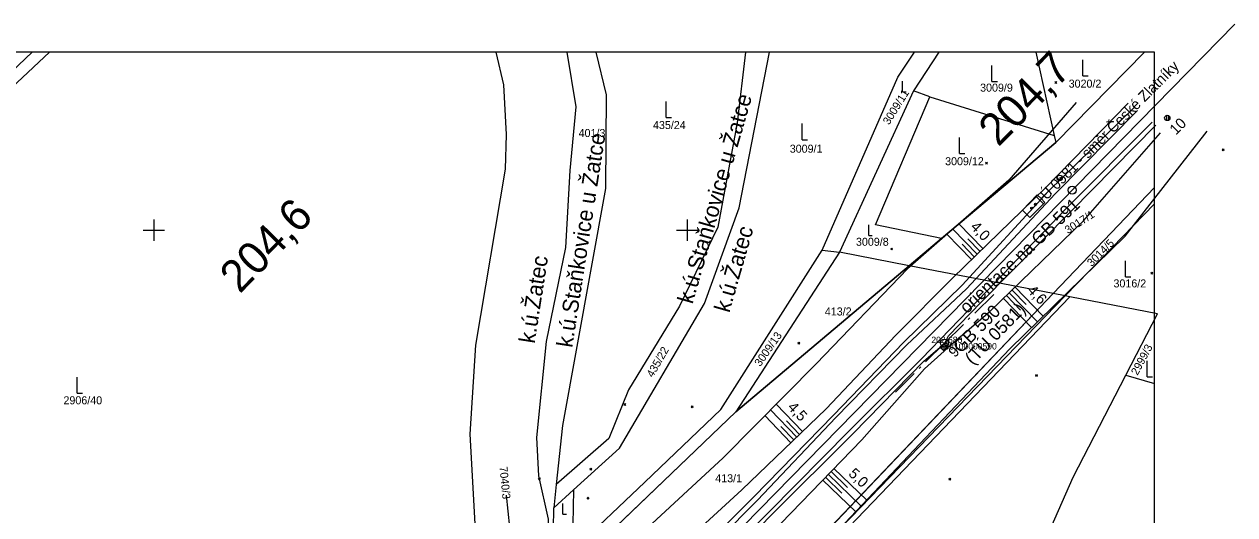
# Model space of a CAD drawing. Extents: x -800194 to -799078, y -1007177 to -1006597.
# Drawn here: x -799524.3 to -799297.3, y -1006853.3 to -1006761.4 of the extents above; entities that cross this region are included whole.
import ezdxf

# ---------------------------------------------------------------- set-up
doc = ezdxf.new("R2010")
doc.units = 0
for name, color, linetype in [('02_Osa_koleje', 7, 'Continuous'), ('Legenda 1', 7, 'Continuous'), ('Ramove udaje', 7, 'Continuous'), ('Vrstva 1', 7, 'Continuous'), ('Vrstva 11', 7, 'Continuous'), ('Vrstva 12', 7, 'Continuous'), ('Vrstva 4', 7, 'Continuous'), ('Vrstva 48', 7, 'Continuous'), ('Vrstva 49', 7, 'Continuous'), ('Vrstva 53', 7, 'Continuous'), ('Vrstva 55', 7, 'Continuous'), ('Vrstva 57', 7, 'Continuous'), ('Vrstva 58', 7, 'Continuous'), ('Vrstva 60', 7, 'Continuous'), ('Vrstva 61', 7, 'Continuous'), ('Vrstva 63', 7, 'Continuous'), ('Vrstva 7', 7, 'Continuous')]:
    doc.layers.add(name, color=color, linetype=linetype)

msp = doc.modelspace()

# ---------------------------------------------------------------- linework, layer by layer
at = {"layer": 'Legenda 1'}
msp.add_lwpolyline([(-800193.4, -1007176.65), (-799312.4, -1007176.65), (-799312.4, -1006766.65), (-800193.4, -1006766.65)], close=True, dxfattribs=at)
at = {"layer": 'Ramove udaje'}
for p, q in [((-799500, -1006798), (-799500, -1006802)), ((-799400, -1006798), (-799400, -1006802)), ((-799502, -1006800), (-799500, -1006800)), ((-799500, -1006800), (-799498, -1006800)), ((-799402, -1006800), (-799400, -1006800)), ((-799400, -1006800), (-799398, -1006800))]:
    msp.add_line(p, q, dxfattribs=at)
at = {"layer": 'Vrstva 1'}
msp.add_line((-799415.71, -1006882.13), (-799297.34, -1006761.4), dxfattribs=at)
at = {"layer": 'Vrstva 11'}
for p, q in [((-799310.17, -1006778.5), (-799310.17, -1006779.43)), ((-799309.79, -1006778.51), (-799309.79, -1006779.42)), ((-799352.27, -1006821.56), (-799352.26, -1006822.23)), ((-799351.9, -1006821.19), (-799351.88, -1006822.6)), ((-799351.52, -1006821.56), (-799351.51, -1006822.22))]:
    msp.add_line(p, q, dxfattribs=at)
msp.add_lwpolyline([(-799351.18, -1006821.88), (-799351.88, -1006822.6), (-799352.6, -1006821.9), (-799351.9, -1006821.19)], close=True, dxfattribs=at)
msp.add_circle((-799309.99, -1006778.96), 0.5, dxfattribs=at)
at = {"layer": 'Vrstva 12'}
msp.add_lwpolyline([(-799352.56, -1006821.89), (-799351.84, -1006822.66), (-799350.97, -1006821.77), (-799351.65, -1006821.04), (-799352.56, -1006821.89)], dxfattribs=at)
at = {"layer": 'Vrstva 4'}
for points in [[(-799415.35, -1006878.39), (-799401.64, -1006864.1), (-799387.49, -1006849.96), (-799372.54, -1006834.62), (-799359.47, -1006821.02), (-799348.43, -1006810.32), (-799332.25, -1006792.66), (-799316.19, -1006777.02)], [(-799414.9, -1006878.87), (-799401.02, -1006864.85), (-799386.83, -1006850.57), (-799372.15, -1006835.07), (-799358.83, -1006821.46), (-799347.62, -1006811), (-799330.98, -1006793.16), (-799315.56, -1006777.54)], [(-799412.39, -1006881.29), (-799398.61, -1006866.93), (-799384.75, -1006852.86), (-799369.47, -1006837.43), (-799356.04, -1006824.08), (-799345.42, -1006813.08), (-799328.8, -1006795.77), (-799312.8, -1006779.76)], [(-799351.01, -1006819.79), (-799344.89, -1006813.48), (-799328.01, -1006796.4), (-799312.11, -1006780.33)], [(-799411.69, -1006881.94), (-799397.91, -1006867.47), (-799384.26, -1006853.37), (-799368.88, -1006838.07), (-799355.62, -1006824.53), (-799352.56, -1006821.89), (-799351.65, -1006821.04), (-799351.01, -1006819.79)]]:
    msp.add_lwpolyline(points, dxfattribs=at)
at = {"layer": 'Vrstva 48'}
for p, q in [((-799345.65, -1006804.46), (-799350.18, -1006799.77)), ((-799344.57, -1006803.42), (-799349.05, -1006798.78)), ((-799346.72, -1006805.51), (-799351.31, -1006800.76)), ((-799345.11, -1006803.94), (-799347.36, -1006801.61)), ((-799346.19, -1006804.98), (-799348.47, -1006802.62)), ((-799339.07, -1006811.2), (-799336.44, -1006813.92)), ((-799338.53, -1006810.68), (-799333.27, -1006816.12)), ((-799340.69, -1006812.77), (-799335.42, -1006818.22)), ((-799340.15, -1006812.24), (-799337.52, -1006814.97)), ((-799339.61, -1006811.72), (-799334.34, -1006817.17)), ((-799379.46, -1006838.77), (-799384.36, -1006833.66)), ((-799378.38, -1006837.73), (-799383.31, -1006832.6)), ((-799380.54, -1006839.81), (-799385.42, -1006834.73)), ((-799378.92, -1006838.25), (-799381.38, -1006835.69)), ((-799380, -1006839.29), (-799382.45, -1006836.74)), ((-799373.02, -1006845.19), (-799369.94, -1006848.17)), ((-799372.5, -1006844.65), (-799366.34, -1006850.6)), ((-799374.58, -1006846.81), (-799368.4, -1006852.78)), ((-799374.06, -1006846.27), (-799370.98, -1006849.26)), ((-799373.54, -1006845.73), (-799367.37, -1006851.69))]:
    msp.add_line(p, q, dxfattribs=at)
at = {"layer": 'Vrstva 49'}
for p, q in [((-799331.05, -1006772.15), (-799330.7, -1006772.5)), ((-799331.05, -1006772.5), (-799330.7, -1006772.15)), ((-799299.69, -1006784.73), (-799299.34, -1006785.09)), ((-799299.69, -1006785.09), (-799299.34, -1006784.73)), ((-799344.05, -1006787.27), (-799343.69, -1006787.63)), ((-799344.05, -1006787.63), (-799343.69, -1006787.27)), ((-799361.83, -1006803.33), (-799361.48, -1006803.69)), ((-799361.83, -1006803.69), (-799361.48, -1006803.33)), ((-799313.07, -1006807.84), (-799312.71, -1006808.2)), ((-799313.07, -1006808.2), (-799312.71, -1006807.84)), ((-799379.24, -1006820.96), (-799378.89, -1006821.31)), ((-799379.24, -1006821.31), (-799378.89, -1006820.96)), ((-799334.71, -1006827), (-799334.35, -1006827.35)), ((-799334.71, -1006827.35), (-799334.35, -1006827)), ((-799411.86, -1006832.45), (-799411.51, -1006832.81)), ((-799411.86, -1006832.81), (-799411.51, -1006832.45)), ((-799399.24, -1006832.89), (-799398.89, -1006833.24)), ((-799399.24, -1006833.24), (-799398.89, -1006832.89)), ((-799418.22, -1006844.55), (-799417.87, -1006844.9)), ((-799418.22, -1006844.9), (-799417.87, -1006844.55)), ((-799427.87, -1006846.74), (-799427.5, -1006846.4)), ((-799427.52, -1006846.75), (-799427.86, -1006846.38)), ((-799350.93, -1006846.42), (-799350.58, -1006846.77)), ((-799350.93, -1006846.77), (-799350.58, -1006846.42)), ((-799418.76, -1006850.02), (-799418.41, -1006850.38)), ((-799418.76, -1006850.38), (-799418.41, -1006850.02))]:
    msp.add_line(p, q, dxfattribs=at)
for points in [[(-799327.09, -1006776.08), (-799339.68, -1006790.63), (-799358.72, -1006807.2), (-799375.73, -1006824.95), (-799393.25, -1006842.64), (-799410.74, -1006858.83), (-799418.52, -1006867.68), (-799420.4, -1006870.81)], [(-799416.02, -1006877.45), (-799404.21, -1006861.9), (-799389.75, -1006848.65), (-799373.94, -1006833.47), (-799360.85, -1006819.66), (-799350.22, -1006808.89), (-799332.89, -1006792.13), (-799317.35, -1006776.17)], [(-799411.24, -1006882.28), (-799396.46, -1006869.34), (-799382.44, -1006854.95), (-799367.28, -1006839.25), (-799355.52, -1006825.99), (-799351.84, -1006822.66), (-799350.97, -1006821.77), (-799343.26, -1006815.25), (-799325.69, -1006798.25), (-799311.27, -1006781.73)], [(-799405.31, -1006888.8), (-799396.79, -1006882.07), (-799386.95, -1006872.93), (-799372.54, -1006857.15), (-799356.35, -1006840.04), (-799339.51, -1006822.21), (-799317.89, -1006801.14), (-799302.5, -1006781.46)]]:
    msp.add_lwpolyline(points, dxfattribs=at)
at = {"layer": 'Vrstva 53'}
for points in [[(-799559.64, -1006968.48), (-799519.68, -1006952.01), (-799500.87, -1006940.41), (-799496.64, -1006937.8), (-799494.85, -1006936.7), (-799484.52, -1006930.32), (-799457.99, -1006908.8), (-799435, -1006885.17), (-799430.26, -1006880.27), (-799425.53, -1006875.38), (-799422.55, -1006864.36), (-799390.88, -1006834), (-799358.35, -1006806.65), (-799352.29, -1006801.56), (-799330.91, -1006783.58), (-799314.24, -1006766.65)], [(-799312.4, -1006791.98), (-799331.37, -1006811.87), (-799413.75, -1006898.23), (-799418.41, -1006902.53), (-799423.07, -1006906.83), (-799433.4, -1006916.39), (-799469.5, -1006946.86), (-799487.22, -1006958.47), (-799495.25, -1006963.74), (-799521.98, -1006977.8), (-799546.71, -1006987.83)]]:
    msp.add_lwpolyline(points, dxfattribs=at)
at = {"layer": 'Vrstva 55'}
for p, q in [((-799352.83, -1006766.65), (-799357.58, -1006773.87)), ((-799334.64, -1006766.65), (-799331.2, -1006782.25)), ((-799314.24, -1006766.65), (-799330.91, -1006783.58)), ((-799357.58, -1006773.87), (-799371.45, -1006804.11)), ((-799354.52, -1006775), (-799357.58, -1006773.87)), ((-799354.52, -1006775), (-799331.2, -1006782.25)), ((-799330.91, -1006783.58), (-799352.29, -1006801.56)), ((-799331.2, -1006782.25), (-799330.91, -1006783.58)), ((-799352.29, -1006801.56), (-799358.35, -1006806.65)), ((-799371.45, -1006804.11), (-799390.88, -1006834)), ((-799374.69, -1006803.75), (-799371.45, -1006804.11)), ((-799358.35, -1006806.65), (-799371.45, -1006804.11)), ((-799358.35, -1006806.65), (-799390.88, -1006834)), ((-799331.37, -1006811.87), (-799358.35, -1006806.65)), ((-799413.75, -1006898.23), (-799331.37, -1006811.87)), ((-799329.14, -1006812.3), (-799331.37, -1006811.87)), ((-799328.26, -1006812.47), (-799329.14, -1006812.3)), ((-799311.83, -1006815.65), (-799328.26, -1006812.47)), ((-799317.77, -1006827.17), (-799311.83, -1006815.65)), ((-799317.77, -1006827.17), (-799312.4, -1006828.72)), ((-799390.88, -1006834), (-799422.55, -1006864.36)), ((-799424.54, -1006847.65), (-799425, -1006852)), ((-799425, -1006852), (-799421.3, -1006848.64)), ((-799421.3, -1006848.64), (-799421.51, -1006860.09))]:
    msp.add_line(p, q, dxfattribs=at)
for points in [[(-799605.96, -1006806.87), (-799585.51, -1006812.81), (-799578.02, -1006814.17), (-799567.46, -1006810.26), (-799560.01, -1006804.4), (-799538.65, -1006784.55), (-799525.56, -1006772.33), (-799519.54, -1006766.65)], [(-799605.25, -1006804.42), (-799586.13, -1006810.77), (-799578.39, -1006811.38), (-799572.8, -1006810.09), (-799568.08, -1006807.93), (-799560.91, -1006802.54), (-799541.14, -1006784.06), (-799522.78, -1006766.65)], [(-799435.89, -1006766.65), (-799434.45, -1006772.74), (-799433.92, -1006782.05), (-799434.12, -1006788.57), (-799439.66, -1006821.53), (-799440.71, -1006838.23), (-799439.23, -1006865.13)], [(-799422.55, -1006766.65), (-799420.88, -1006776.85), (-799422, -1006788.79), (-799422.77, -1006803.25), (-799426.4, -1006820.84), (-799428.26, -1006838.83), (-799427.88, -1006846.03), (-799426.08, -1006854.14), (-799425.53, -1006875.38)], [(-799417.14, -1006766.65), (-799415.15, -1006774.66), (-799415.3, -1006792.16), (-799423.37, -1006836.59), (-799424.54, -1006847.65)], [(-799389.07, -1006766.65), (-799390.61, -1006779.89), (-799394.27, -1006799.42), (-799401.41, -1006814.24), (-799411, -1006829.93), (-799414.66, -1006839), (-799424.54, -1006847.65)], [(-799421.3, -1006848.64), (-799412.65, -1006840.8), (-799396.76, -1006813.74), (-799390.24, -1006795.83), (-799384.58, -1006766.65)], [(-799374.69, -1006803.75), (-799360.51, -1006771.31), (-799357.35, -1006766.65)], [(-799352.29, -1006801.56), (-799364.7, -1006799), (-799354.52, -1006775)], [(-799312.4, -1006791.98), (-799331.37, -1006811.87)], [(-799312.4, -1006795.04), (-799322.34, -1006805.27), (-799329.14, -1006812.3)], [(-799421.51, -1006860.09), (-799407.9, -1006847.2), (-799393.66, -1006833.58), (-799374.69, -1006803.75)], [(-799329.14, -1006812.3), (-799409.48, -1006895.36), (-799407.32, -1006903.81)], [(-799328.26, -1006812.47), (-799403.59, -1006891), (-799407.32, -1006903.81)], [(-799364.81, -1006930.69), (-799327.63, -1006846.25), (-799317.77, -1006827.17)], [(-799423.86, -1006862.12), (-799425.1, -1006860), (-799425, -1006852)]]:
    msp.add_lwpolyline(points, dxfattribs=at)
at = {"layer": 'Vrstva 58'}
for p, q in [((-799325.85, -1006771.07), (-799325.85, -1006768.07)), ((-799342.86, -1006772.12), (-799342.86, -1006769.12)), ((-799359.6, -1006774.08), (-799359.6, -1006772.07)), ((-799342.86, -1006772.12), (-799341.85, -1006772.12)), ((-799325.85, -1006771.07), (-799324.85, -1006771.07)), ((-799359.6, -1006774.08), (-799358.93, -1006774.08)), ((-799403.93, -1006778.9), (-799403.93, -1006775.9)), ((-799403.93, -1006778.9), (-799402.93, -1006778.9)), ((-799378.46, -1006783.03), (-799378.46, -1006780.03)), ((-799378.46, -1006783.03), (-799377.46, -1006783.03)), ((-799348.92, -1006785.62), (-799348.92, -1006782.62)), ((-799348.92, -1006785.62), (-799347.92, -1006785.62)), ((-799365.97, -1006800.98), (-799365.97, -1006798.97)), ((-799365.97, -1006800.98), (-799365.3, -1006800.98)), ((-799317.81, -1006808.74), (-799317.81, -1006805.74)), ((-799317.81, -1006808.74), (-799316.81, -1006808.74)), ((-799313.77, -1006827.47), (-799313.77, -1006824.47)), ((-799514.35, -1006830.52), (-799514.35, -1006827.52)), ((-799313.77, -1006827.47), (-799312.77, -1006827.47)), ((-799514.35, -1006830.52), (-799513.35, -1006830.52)), ((-799433.93, -1006849.66), (-799433.29, -1006855.63)), ((-799423.31, -1006853.2), (-799423.31, -1006851.19)), ((-799423.31, -1006853.2), (-799422.64, -1006853.2))]:
    msp.add_line(p, q, dxfattribs=at)
at = {"layer": 'Vrstva 60'}
msp.add_line((-799351.77, -1006821.14), (-799351.77, -1006821.14), dxfattribs=at)
at = {"layer": 'Vrstva 63'}
for p, q in [((-799346.08, -1006815.52), (-799342.52, -1006812.01)), ((-799351.77, -1006821.14), (-799348.21, -1006817.63)), ((-799347.29, -1006816.72), (-799347, -1006816.44)), ((-799351.77, -1006821.14), (-799355.3, -1006824.68)), ((-799351.81, -1006821.18), (-799351.74, -1006821.1)), ((-799357.42, -1006826.81), (-799360.95, -1006830.35)), ((-799356.22, -1006825.6), (-799356.5, -1006825.89))]:
    msp.add_line(p, q, dxfattribs=at)
msp.add_circle((-799351.77, -1006821.14), 0.756, dxfattribs=at)
at = {"layer": 'Vrstva 7'}
for p, q in [((-799330.14, -1006790.15), (-799330.21, -1006790.22)), ((-799331.71, -1006793.18), (-799332.78, -1006792.13)), ((-799334.89, -1006795.16), (-799334.5, -1006795.16)), ((-799335.6, -1006795.87), (-799335.2, -1006795.87))]:
    msp.add_line(p, q, dxfattribs=at)
msp.add_lwpolyline([(-799332.25, -1006792.66), (-799333.65, -1006794.08), (-799334.36, -1006793.38), (-799337.16, -1006796.24), (-799335.73, -1006797.64), (-799332.93, -1006794.78), (-799333.65, -1006794.08)], dxfattribs=at)
for centre, radius in [((-799330.17, -1006790.19), 0.5), ((-799327.82, -1006792.49), 0.75), ((-799327.82, -1006792.5), 0.75), ((-799334.7, -1006795.15), 0.2), ((-799335.4, -1006795.87), 0.2)]:
    msp.add_circle(centre, radius, dxfattribs=at)

# ---------------------------------------------------------------- texts
at = {"layer": '02_Osa_koleje'}
msp.add_text('TÚ 0581 - směr České Zlatníky', height=2, rotation=45.0156, dxfattribs=at).set_placement((-799333.79, -1006795.62))
at = {"layer": 'Vrstva 11'}
for s, rotation, p in [('10', 45.1644, (-799308.36, -1006782.26)), ('9', 46.0125, (-799349.81, -1006823.96))]:
    msp.add_text(s, height=2, rotation=rotation, dxfattribs=at).set_placement(p)
at = {"layer": 'Vrstva 48'}
for s, rotation, p in [('4,0', 314.0186, (-799347.02, -1006799.5)), ('4,6', 314.047, (-799336.39, -1006811.41)), ('4,5', 313.8297, (-799381.3, -1006833.28)), ('5,0', 315.993, (-799369.9, -1006845.78))]:
    msp.add_text(s, height=2, rotation=rotation, dxfattribs=at).set_placement(p)
at = {"layer": 'Vrstva 55'}
for s, rotation, p in [('k.ú.Staňkovice u Žatce', 73.9881, (-799398.99, -1006813.95)), ('k.ú.Staňkovice u Žatce', 81.1486, (-799421.54, -1006822.1)), ('k.ú.Žatec', 73.9881, (-799392.1, -1006815.59)), ('k.ú.Žatec', 81.1486, (-799428.59, -1006821.32))]:
    msp.add_text(s, height=3, rotation=rotation, dxfattribs=at).set_placement(p)
at = {"layer": 'Vrstva 57'}
for s, p in [('3009/9', (-799345.08, -1006774.03)), ('3020/2', (-799328.48, -1006773.28)), ('435/24', (-799406.4, -1006781.04)), ('401/3', (-799420.34, -1006782.53)), ('3009/1', (-799380.76, -1006785.47)), ('3009/12', (-799351.64, -1006787.82)), ('3009/8', (-799368.35, -1006802.91)), ('3016/2', (-799320.08, -1006810.71)), ('413/2', (-799374.19, -1006815.97)), ('2906/40', (-799516.91, -1006832.61)), ('413/1', (-799394.73, -1006847.22))]:
    msp.add_text(s, height=1.5, dxfattribs=at).set_placement(p)
for s, rotation, p in [('3009/11', 58, (-799362.16, -1006780.37)), ('3017/1', 33, (-799328.61, -1006800.75)), ('3014/5', 45, (-799324.15, -1006806.92)), ('3009/13', 55, (-799386.29, -1006825.65)), ('435/22', 60.1157, (-799406.42, -1006827.7)), ('2999/3', 61.8819, (-799315.57, -1006827.28)), ('7040/3', 275.5855, (-799435.19, -1006844.32))]:
    msp.add_text(s, height=1.5, rotation=rotation, dxfattribs=at).set_placement(p)
at = {"layer": 'Vrstva 60'}
msp.add_text('58100000590', height=1.2, dxfattribs=at).set_placement((-799351.77, -1006822.34))
at = {"layer": 'Vrstva 61'}
msp.add_text('202.680', height=1.2, dxfattribs=at).set_placement((-799354.22, -1006821.14))
at = {"layer": 'Vrstva 63'}
for s, rotation, p in [('orientace na GB 591', 43.4761, (-799347.54, -1006815.76)), ('GB 590', 45.6148, (-799348.69, -1006823.18)), ('(TÚ 0581)', 45.6148, (-799346.47, -1006825.35))]:
    msp.add_text(s, height=2.4, rotation=rotation, dxfattribs=at).set_placement(p)
at = {"layer": 'Vrstva 7'}
for s, p in [('204,7', (-799341.65, -1006784.52)), ('204,6', (-799483.87, -1006812.02))]:
    msp.add_text(s, height=6, rotation=45.5634, dxfattribs=at).set_placement(p)

doc.saveas('drawing.dxf')
